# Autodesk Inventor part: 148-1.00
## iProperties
Created: 2007-06
Part Number: 148-1.00
Document SubType Name: Modeling
Designer: btaylor
Density: 1 g/cm^3
Author: btaylor
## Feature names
1. Extrusion1
2. Extrusion2
3. Fillet1
4. Fillet2
5. Chamfer1
6. Chamfer2
